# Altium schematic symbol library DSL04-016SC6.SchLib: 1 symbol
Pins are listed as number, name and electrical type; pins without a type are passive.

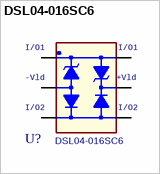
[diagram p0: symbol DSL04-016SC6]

## DSL04-016SC6
designator U?
footprint ST_SOT23-6L
pins: 1 I/O1, 2 -Vld, 3 I/O2, 4 I/O2b, 5 +Vld, 6 I/O1b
